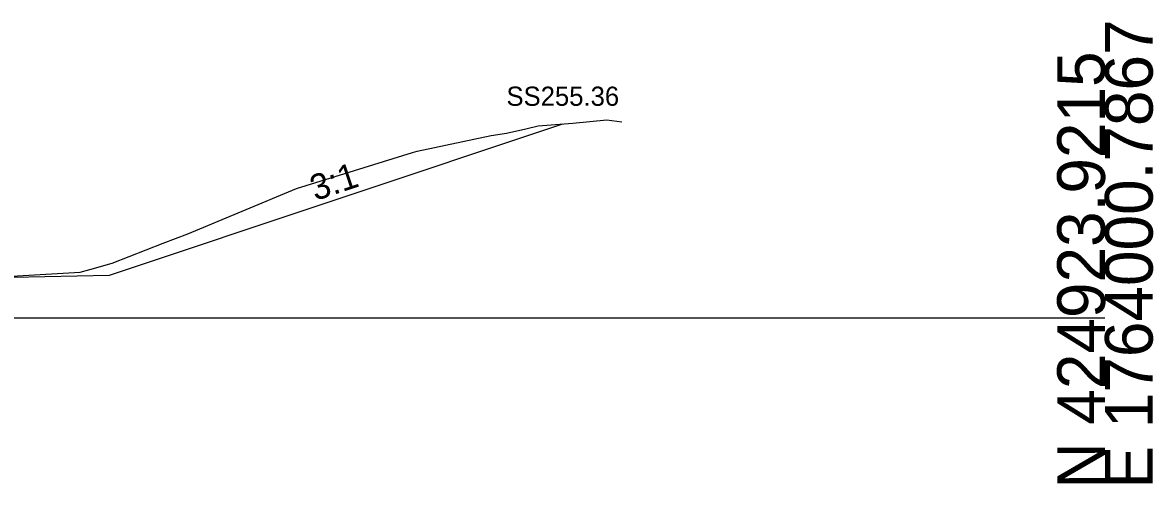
# Model space of a CAD drawing. Extents: x -26 to 3203, y -11010 to 4024.
# Drawn here: x 3136.5 to 3202.8, y -4009.7 to -3982.7 of the extents above; entities that cross this region are included whole.
import ezdxf

# ---------------------------------------------------------------- set-up
doc = ezdxf.new("R2010")
doc.units = 0
for name, color, linetype in [('Exist Cross Section Cell', 7, 'Continuous'), ('Exist XS Ground Line', 7, 'Continuous'), ('Prop CMT Slope Grass', 7, 'Continuous'), ('Prop XS Side Slope Text', 7, 'Continuous'), ('Prop XS SS Elevation Text', 7, 'Continuous'), ('Scratch_Level_0', 7, 'Continuous')]:
    doc.layers.add(name, color=color, linetype=linetype)

msp = doc.modelspace()

# ---------------------------------------------------------------- linework, layer by layer
at = {"layer": 'Exist Cross Section Cell'}
msp.add_line((3100, -4000), (3200, -4000), dxfattribs=at)
at = {"layer": 'Exist XS Ground Line'}
msp.add_lwpolyline([(3134.197, -3997.662), (3139.897, -3997.314), (3140.477, -3997.165), (3141.772, -3996.793), (3144.775, -3995.629), (3146.211, -3995.075), (3152.585, -3992.415), (3159.399, -3990.317), (3159.676, -3990.232), (3164.015, -3989.314), (3164.896, -3989.177), (3166.044, -3988.929), (3166.767, -3988.746), (3168.802, -3988.591), (3170.795, -3988.407), (3171.661, -3988.507)], dxfattribs=at)
msp.add_lwpolyline([(3134.197, -3997.662), (3139.897, -3997.314), (3140.477, -3997.165), (3141.772, -3996.793), (3144.775, -3995.629), (3146.211, -3995.075), (3152.585, -3992.415), (3159.399, -3990.317), (3159.676, -3990.232), (3164.015, -3989.314), (3164.896, -3989.177), (3166.044, -3988.929), (3166.767, -3988.746), (3168.802, -3988.591), (3170.795, -3988.407), (3171.661, -3988.507)], dxfattribs=at)
msp.add_lwpolyline([(3134.197, -3997.662), (3139.897, -3997.314), (3140.477, -3997.165), (3141.772, -3996.793), (3144.775, -3995.629), (3146.211, -3995.075), (3152.585, -3992.415), (3159.399, -3990.317), (3159.676, -3990.232), (3164.015, -3989.314), (3164.896, -3989.177), (3166.044, -3988.929), (3166.767, -3988.746), (3168.802, -3988.591), (3170.795, -3988.407), (3171.661, -3988.507)], dxfattribs=at)
msp.add_lwpolyline([(3134.197, -3997.662), (3139.897, -3997.314), (3140.477, -3997.165), (3141.772, -3996.793), (3144.775, -3995.629), (3146.211, -3995.075), (3152.585, -3992.415), (3159.399, -3990.317), (3159.676, -3990.232), (3164.015, -3989.314), (3164.896, -3989.177), (3166.044, -3988.929), (3166.767, -3988.746), (3168.802, -3988.591), (3170.795, -3988.407), (3171.661, -3988.507)], dxfattribs=at)
msp.add_lwpolyline([(3134.197, -3997.662), (3139.897, -3997.314), (3140.477, -3997.165), (3141.772, -3996.793), (3144.775, -3995.629), (3146.211, -3995.075), (3152.585, -3992.415), (3159.399, -3990.317), (3159.676, -3990.232), (3164.015, -3989.314), (3164.896, -3989.177), (3166.044, -3988.929), (3166.767, -3988.746), (3168.802, -3988.591), (3170.795, -3988.407), (3171.661, -3988.507)], dxfattribs=at)
at = {"layer": 'Prop CMT Slope Grass'}
msp.add_lwpolyline([(3132.123, -3997.689), (3141.623, -3997.499), (3168.214, -3988.636)], dxfattribs=at)

# ---------------------------------------------------------------- texts
at = {"layer": 'Exist Cross Section Cell'}
for s, p in [('E 1764000.7867', (3202.8, -4010)), ('N 424923.9215', (3200, -4010))]:
    msp.add_text(s, height=2.8, rotation=90, dxfattribs=at).set_placement(p)
at = {"layer": 'Prop XS Side Slope Text'}
msp.add_text('3:1', height=1.5, rotation=18.43493, dxfattribs=at).set_placement((3153.696, -3993.159))
at = {"layer": 'Prop XS SS Elevation Text'}
msp.add_text('SS255.36', height=1.125, dxfattribs=at).set_placement((3164.903, -3987.577))
at = {"layer": 'Scratch_Level_0'}
for s, p in [('Exterior Boundary', (3168.055, -3988.646)), ('RT_Slope_Cut', (3168.11, -3988.646)), ('RT_CSLP_Pnt', (3141.524, -3997.509))]:
    msp.add_text(s, height=0.02, dxfattribs=at).set_placement(p)

doc.saveas('drawing.dxf')
